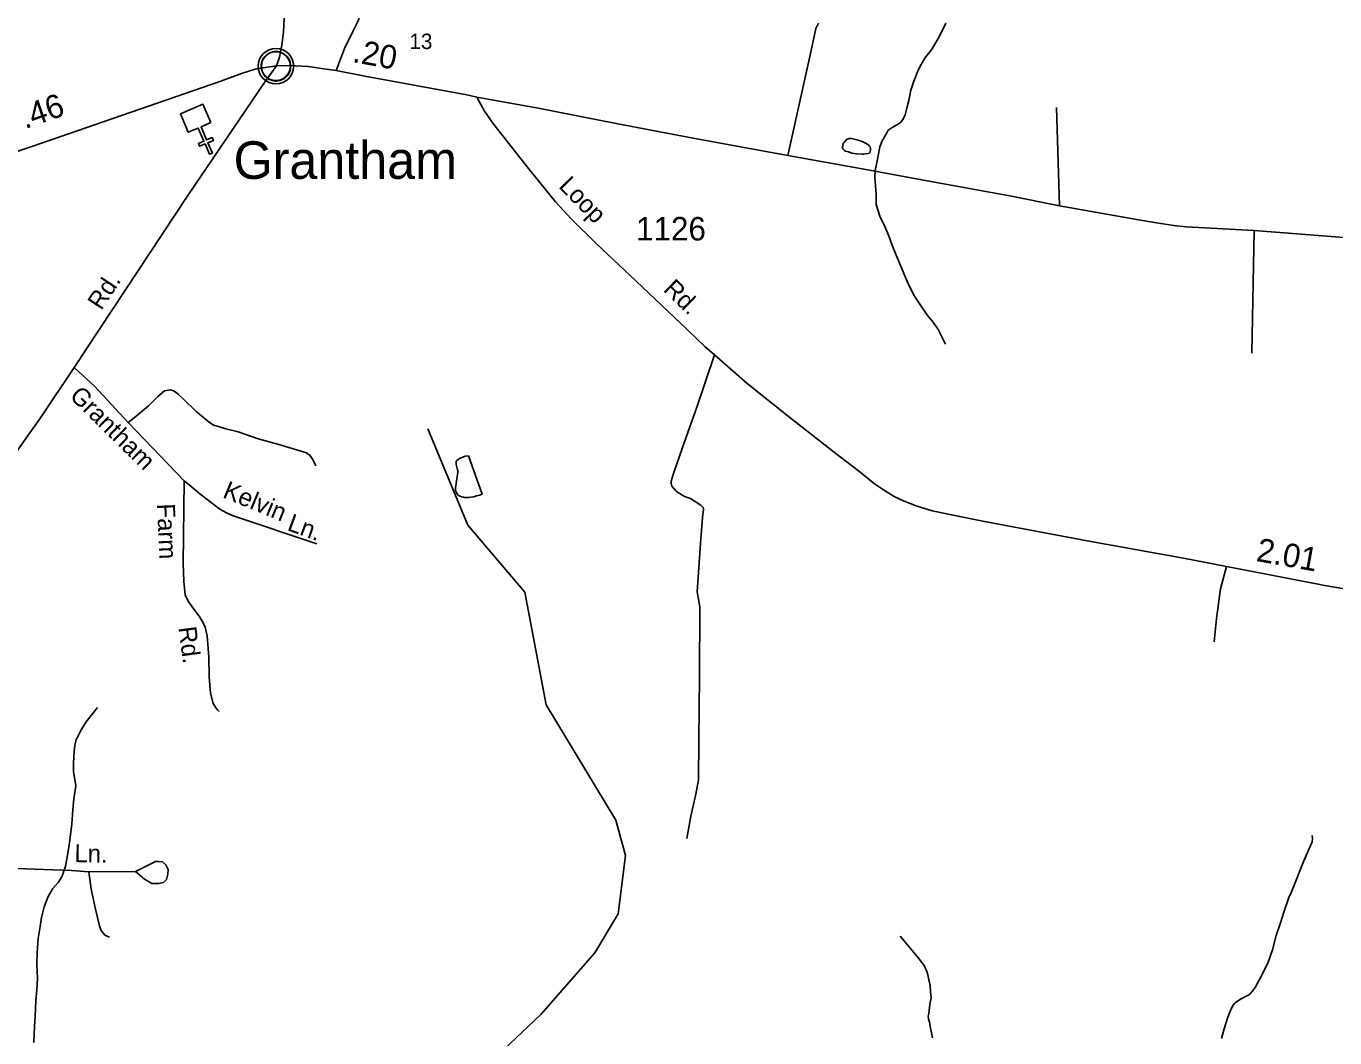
# Model space of a CAD drawing. Extents: x 2206922 to 2357709, y 510027 to 673830.
# Drawn here: x 2248244 to 2255208, y 558977 to 564362 of the extents above; entities that cross this region are included whole.
import ezdxf

# ---------------------------------------------------------------- set-up
doc = ezdxf.new("R2010")
doc.units = 0
for name, color, linetype in [('Exist Civil Demographics Community CELL', 7, 'Continuous'), ('Exist Civil Demographics Community Label', 7, 'Continuous'), ('Exist Cultural Church CELL', 7, 'Continuous'), ('Exist Hydrographic Misc Water Feature', 7, 'Continuous'), ('Exist Road Non-System Type 51', 7, 'Continuous'), ('Exist Road Non-System Type 51 Label', 7, 'Continuous'), ('Exist Road Primary US Attributed', 7, 'Continuous'), ('Exist Road Primary US Label', 7, 'Continuous'), ('Exist Road Primary US Mileage Hundredths English Label', 7, 'Continuous'), ('Exist Road Secondary Mileage Hundredths English Label', 7, 'Continuous'), ('Exist Road Secondary Type 51 Attributed', 7, 'Continuous'), ('Exist Road Secondary Type 51 Label', 7, 'Continuous'), ('Exist Road Secondary Type 51 Number Label', 7, 'Continuous')]:
    doc.layers.add(name, color=color, linetype=linetype)

msp = doc.modelspace()

# ---------------------------------------------------------------- linework, layer by layer
at = {"layer": 'Exist Civil Demographics Community CELL'}
msp.add_lwpolyline([(2249495.4, 564161.4), (2249496.4, 564167), (2249498.2, 564173.6), (2249501.1, 564180.8), (2249504, 564186.5), (2249507.4, 564192.3), (2249511.1, 564197.4), (2249515.1, 564201.8), (2249519.7, 564206.4), (2249525.2, 564211), (2249530.7, 564214.6), (2249535.5, 564217.5), (2249540.6, 564219.9), (2249546, 564222.2), (2249551.7, 564224), (2249556, 564225.2), (2249560.9, 564225.9), (2249565, 564226.7), (2249571.4, 564226.9), (2249575.8, 564226.8), (2249581.4, 564226.6), (2249586.4, 564225.8), (2249591.3, 564224.8), (2249596.3, 564223.4), (2249601.4, 564221.5), (2249608.1, 564218.6), (2249614.3, 564215.1), (2249619.4, 564211.5), (2249624.6, 564207.5), (2249627.9, 564204.4), (2249632, 564200), (2249635.9, 564195.3), (2249638.9, 564190.7), (2249642.1, 564185.7), (2249644.5, 564180.5), (2249646.6, 564175.5), (2249648.1, 564170.5), (2249649.4, 564165.9), (2249650.5, 564159.9), (2249651.1, 564155.2), (2249651.4, 564149.2), (2249651.2, 564143.4), (2249650.6, 564137.7), (2249649.7, 564132.2), (2249648.1, 564126.1), (2249646.2, 564120.2), (2249643.9, 564115.2), (2249640.7, 564109.2), (2249637.4, 564103.8), (2249634, 564099.1), (2249629.8, 564094.4), (2249624.5, 564089.4), (2249619.5, 564085.3), (2249614.5, 564081.9), (2249610.1, 564079.4), (2249603.3, 564076.1), (2249596.2, 564073.4), (2249590.2, 564071.9), (2249583.6, 564070.6), (2249579.2, 564070.2), (2249574.7, 564069.9), (2249569.1, 564069.9), (2249564.8, 564070.3), (2249559.2, 564071.1), (2249553.3, 564072.4), (2249548.7, 564073.7), (2249543.5, 564075.5), (2249538.9, 564077.5), (2249535, 564079.8), (2249528.2, 564083.8), (2249522.6, 564088.1), (2249517.7, 564092.6), (2249513.2, 564097.5), (2249510.1, 564101.4), (2249507.1, 564105.6), (2249503, 564112.7), (2249501.3, 564116.2), (2249499.6, 564120.3), (2249497, 564128.5), (2249495.4, 564135.5), (2249494.8, 564140.7), (2249494.4, 564147), (2249494.4, 564151.7), (2249494.9, 564158.1)], close=True, dxfattribs=at)
for centre, radius in [((2249573, 564149), 94.3), ((2249572.8, 564149.3), 76.7)]:
    msp.add_circle(centre, radius, dxfattribs=at)
at = {"layer": 'Exist Cultural Church CELL'}
msp.add_lwpolyline([(2249226.3, 563848.6), (2249174.1, 563826), (2249204.2, 563756.1), (2249233.6, 563768.7), (2249239.9, 563754.1), (2249210.5, 563741.4), (2249234.4, 563686.2), (2249219.6, 563679.8), (2249195.8, 563735), (2249166.4, 563722.4), (2249160.1, 563737), (2249189.5, 563749.7), (2249159.4, 563819.6), (2249106.4, 563796.9), (2249064.2, 563894.7), (2249184.2, 563946.4)], close=True, dxfattribs=at)
at = {"layer": 'Exist Hydrographic Misc Water Feature'}
for points in [[(2253136.7, 562669.2), (2253096.1, 562747.1), (2253069.4, 562786.8), (2253040.9, 562822.3), (2252998.7, 562882.2), (2252966.7, 562929.6), (2252931.6, 563003.4), (2252911.3, 563055.1), (2252882.8, 563121.1), (2252858.2, 563182.8), (2252832.2, 563250.4), (2252813.5, 563296.2), (2252787.1, 563350), (2252766.8, 563411.9), (2252766.4, 563468), (2252759.4, 563555.8), (2252761.4, 563593.6), (2252769.2, 563627.7), (2252782, 563691.9), (2252785.8, 563719.7), (2252799.6, 563752.1), (2252821.7, 563790.1), (2252831.6, 563808.1), (2252851.3, 563822.5), (2252880.8, 563838.8), (2252897, 563848.9), (2252910.5, 563866.7), (2252921, 563890.7), (2252930, 563925), (2252940, 563966.9), (2252945.6, 563993.2), (2252951.5, 564021.1), (2252967.1, 564069.1), (2252986.6, 564119.2), (2253000.5, 564149.6), (2253026.2, 564191.5), (2253065.7, 564242), (2253105.1, 564312.3), (2253138.5, 564378.6)], [(2252623.7, 563764.4), (2252635.5, 563764.6), (2252649.9, 563760.9), (2252671.8, 563755.1), (2252692.1, 563747.2), (2252710, 563739.2), (2252726.2, 563729.5), (2252729.7, 563725.3), (2252734.2, 563719.3), (2252736.2, 563713.3), (2252736.2, 563707.7), (2252736.4, 563701.6), (2252734.2, 563695.5), (2252734.4, 563691.4), (2252730.3, 563685.5), (2252722.3, 563683.4), (2252710.4, 563683.2), (2252700.3, 563681.1), (2252692.1, 563681.1), (2252664.5, 563682.8), (2252638.2, 563686.7), (2252620.6, 563692.7), (2252604.2, 563696.4), (2252598.4, 563700.5), (2252594.1, 563704.4), (2252590, 563708.2), (2252588, 563714.2), (2252590, 563726.5), (2252592.1, 563738.4), (2252596.2, 563742.2), (2252599.9, 563746.5), (2252604.2, 563752.4), (2252607.9, 563756.3), (2252612, 563760.5), (2252617.7, 563762.5), (2252623.7, 563764.4)], [(2250677.5, 556575.6), (2250643.5, 556760), (2250532.5, 556981.9), (2250530.5, 557283.7), (2250634.4, 557750.6), (2250640.4, 558058.8), (2250496.4, 558432.3), (2250544.4, 558624.9), (2250618.4, 558757.8), (2250982.4, 559101.4), (2251270.5, 559430.1), (2251394.4, 559637.5), (2251433.5, 559948.3), (2251381.4, 560136.3), (2251010.5, 560750.5), (2250897.5, 561349.8), (2250594.5, 561706.8), (2250381.4, 562219.4)], [(2250624.6, 561857.4), (2250610.7, 561855), (2250598.4, 561852.8), (2250586.5, 561853), (2250576.2, 561852.9), (2250570.7, 561855), (2250562.5, 561856.6), (2250552.4, 561860.5), (2250544.6, 561864.5), (2250536, 561874.3), (2250532.1, 561884.3), (2250528, 561890.5), (2250528, 561902.3), (2250530.1, 561914.6), (2250533.8, 561940.4), (2250541.3, 561988.3), (2250541.1, 561994.4), (2250539.1, 562000.4), (2250532.7, 562028.5), (2250531.1, 562038.1), (2250531.1, 562046.2), (2250535.2, 562050.5), (2250542.6, 562056.3), (2250550.4, 562060.3), (2250558.8, 562064.4), (2250566.6, 562068.4), (2250580.5, 562072.8), (2250596.7, 562074.9), (2250670.3, 561871.6), (2250656.2, 561865.6), (2250640.6, 561861.4), (2250624.6, 561857.4)], [(2248624.1, 560735.6), (2248563.4, 560658.8), (2248549.5, 560637), (2248535.9, 560616.7), (2248519.9, 560584.7), (2248509.9, 560562.7), (2248502.3, 560534.6), (2248496.8, 560480.7), (2248495.1, 560430.7), (2248495.5, 560394.5), (2248508.1, 560318.8), (2248496.8, 560248.7), (2248491.2, 560190.8), (2248487.5, 560116.7), (2248476.7, 560028.7), (2248465, 559958.7), (2248453.3, 559890.4), (2248436.1, 559838.2), (2248414.1, 559804.2), (2248386.3, 559771.9), (2248361, 559729.9), (2248339.7, 559675.5), (2248325.8, 559617.6), (2248318.2, 559569.7), (2248306.7, 559505.3), (2248301.6, 559433.5), (2248299.9, 559365.6), (2248304.4, 559295.6), (2248300.9, 559233.7), (2248295.6, 559173.6), (2248292.1, 559091.4), (2248288.6, 559037.6), (2248285, 558951.8)], [(2255086.5, 560054.4), (2255089.2, 560038.7), (2255086.9, 560020.7), (2255042.2, 559920), (2254977, 559753.8), (2254963.5, 559723.9), (2254938.3, 559651.4), (2254918.6, 559589.5), (2254895.4, 559521.2), (2254875.9, 559445.1), (2254852.6, 559380.9), (2254819.1, 559310.5), (2254783.5, 559244.5), (2254773.8, 559230.5), (2254757.6, 559212.3), (2254746.1, 559204.3), (2254706.2, 559184), (2254678.1, 559163.5), (2254666.4, 559151.5), (2254656.7, 559131.5), (2254638.7, 559087.5), (2254619.4, 559025.1), (2254604, 558973.1)], [(2252894.3, 559518.8), (2252922.2, 559485), (2252948.9, 559453.4), (2252993, 559401.7), (2253009.4, 559377.8), (2253021.7, 559362.1), (2253027.8, 559350.2), (2253035.6, 559336.1), (2253041.8, 559312.1), (2253046.5, 559286.2), (2253054.7, 559256.2), (2253056.5, 559222.2), (2253059, 559190.6), (2253053.2, 559156.2), (2253051.2, 559138.3), (2253047.5, 559106.4), (2253043.8, 559092.3), (2253045.9, 559078.2), (2253050.2, 559060.6), (2253056.1, 559030.5), (2253066.8, 558976.6)]]:
    msp.add_lwpolyline(points, dxfattribs=at)
at = {"layer": 'Exist Road Non-System Type 51'}
for p, q in [((2253741.8, 563406.5), (2253726.4, 563929.3)), ((2254766.4, 562621.2), (2254778.6, 563273.5)), ((2249084.4, 561942.2), (2248786, 562252.7)), ((2248825.9, 559863.2), (2248576.6, 559861.2))]:
    msp.add_line(p, q, dxfattribs=at)
for points in [[(2249892.5, 564126), (2249937.6, 564242.2), (2249984.7, 564336.6), (2250004.4, 564378.8), (2250014.4, 564398.8), (2250012, 564430.8), (2250005.4, 564498.8), (2250009, 564568.7), (2250014.4, 564638.7), (2250018, 564686.6), (2250019.9, 564700.6), (2250033.5, 564740.7), (2250082.9, 564819.1)], [(2252297.3, 563672.7), (2252363.7, 563977.6), (2252416.8, 564216.3), (2252445.7, 564350.1), (2252459.4, 564377.5)], [(2251760.3, 560039.2), (2251780, 560157.8), (2251807.4, 560274.9), (2251821.1, 560350.9), (2251822.6, 560562.3), (2251827.2, 560898.3), (2251828.7, 561270.9), (2251815, 561351.5), (2251831.7, 561608.4), (2251842.4, 561746.8), (2251848.2, 561791.1), (2251846.1, 561800.6), (2251834.8, 561812.2), (2251778.5, 561847.2), (2251746.6, 561859.3), (2251728.5, 561869.2), (2251707.5, 561884.3), (2251703.1, 561887.7), (2251679.7, 561914.1), (2251675.7, 561927.8), (2251675.2, 561939.9), (2251687.3, 561976.4), (2251736, 562119.4), (2251813.5, 562333.8), (2251906.2, 562612.1)], [(2248786, 562252.7), (2248607.3, 562446.2), (2248498.4, 562545.1)], [(2249785, 562021.4), (2249768.4, 562054.7), (2249761, 562067.6), (2249753.6, 562078.7), (2249742.5, 562086.1), (2249735.1, 562091.6), (2249694.4, 562102.7), (2249589.1, 562136), (2249478.2, 562165.6), (2249371, 562202.6), (2249306.3, 562219.2), (2249267.5, 562230.3), (2249239.8, 562237.7), (2249210.2, 562259.9), (2249147.4, 562313.5), (2249079, 562378.3), (2249054.5, 562400.8), (2249042.2, 562411.4), (2249027.2, 562420.3), (2249011.1, 562425.9), (2248979.9, 562421.4), (2248943.8, 562391.4), (2248894.2, 562341.3), (2248818.4, 562276.6), (2248786, 562252.7)], [(2249084.4, 561942.2), (2249079.6, 561504), (2249082, 561405.7), (2249090.3, 561335.8), (2249098.6, 561315.6), (2249111.6, 561293.1), (2249119.9, 561281.3), (2249135.3, 561258.8), (2249163.7, 561220.9), (2249185, 561186.5), (2249196.8, 561162.9), (2249207.5, 561117.8), (2249215.8, 561003), (2249218.1, 560898.7), (2249225.2, 560812.3), (2249239.5, 560756.6), (2249254.8, 560731.7), (2249261.9, 560723.4), (2249270.2, 560714)], [(2249791.1, 561605.8), (2249344.8, 561755.1), (2249309.3, 561771.6), (2249275, 561791.8), (2249227.6, 561826.1), (2249167.2, 561873.5), (2249122.3, 561911.4), (2249084.4, 561942.2)], [(2254565.8, 561085.3), (2254578, 561208.5), (2254599.2, 561366.7), (2254631.2, 561485.3)], [(2248576.6, 559861.2), (2248485.4, 559868.3), (2247846.2, 559890.8), (2247384.5, 559906.2), (2247223.5, 559907.4), (2247164.3, 559914.5), (2247109.9, 559922.8), (2247076.1, 559937)], [(2248825.9, 559863.2), (2248931.3, 559916.1), (2248949.3, 559916.3), (2248969.3, 559914.5), (2248987.5, 559898.5), (2248999.6, 559872.7), (2248997.9, 559848.7), (2248990.2, 559820.7), (2248974.2, 559804.4), (2248948.3, 559798.4), (2248912.3, 559798.1), (2248874.2, 559821.6), (2248825.9, 559863.2)], [(2248576.6, 559861.2), (2248589.6, 559769.4), (2248612.1, 559662.8), (2248633.4, 559574), (2248642.8, 559548.5), (2248663, 559524.2), (2248686.6, 559513.6)]]:
    msp.add_lwpolyline(points, dxfattribs=at)
at = {"layer": 'Exist Road Primary US Attributed'}
for points in [[(2247268.5, 563382.4), (2248278.6, 563722.9), (2249084, 564001.3), (2249279.3, 564069), (2249388.9, 564109.7), (2249462.8, 564132.4), (2249504.7, 564140.8), (2249576.5, 564151.3)], [(2249576.5, 564151.3), (2249642.5, 564151.8), (2249744.6, 564146.7), (2249828.5, 564135.4), (2249892.5, 564126), (2250046.8, 564095.2), (2250589.3, 563995.7), (2250642, 563984.6)], [(2250642, 563984.6), (2250959.8, 563926.6), (2251383.8, 563844.3), (2251792.7, 563765.1), (2252297.3, 563672.7), (2252692, 563603.4), (2253077.8, 563530.8), (2253486.3, 563457.5), (2253741.8, 563406.5), (2254163.1, 563331.3), (2254258.8, 563314.6), (2254351.5, 563300.9), (2254416.9, 563293.3), (2254778.6, 563273.5), (2255279.3, 563236.1), (2256037.4, 563182.4), (2256635.4, 563141.3), (2256953.4, 563126), (2257076.5, 563118.4), (2257768, 563063.7), (2257898.7, 563045.4), (2258552.2, 562960.3), (2259081.1, 562884.2)]]:
    msp.add_lwpolyline(points, dxfattribs=at)
at = {"layer": 'Exist Road Secondary Type 51 Attributed'}
for points in [[(2249576.5, 564151.3), (2249592, 564197.4), (2249604.6, 564260.6), (2249613.6, 564332.3), (2249616.1, 564400.1), (2249600.8, 564769.8), (2249586.7, 565008.4), (2249562.4, 565412.7), (2249558, 565680.4), (2249561.2, 565780.4), (2249568.4, 565870.4), (2249596.8, 566068.5), (2249648.3, 566376.8), (2249736.1, 566895.3), (2249782.4, 567233.9), (2249790.1, 567292.7)], [(2246051.8, 556756.8), (2246064.4, 556788.3), (2246513.3, 558143.2), (2246748.8, 558892.9), (2247076.1, 559937), (2247140.7, 560160.3), (2247185.6, 560316.6), (2247227.1, 560441.5), (2247291, 560613.3), (2247372.7, 560802.8), (2247415.3, 560907), (2247502.9, 561056.3), (2247655.8, 561326), (2247768, 561513.4), (2247919.6, 561731.4), (2248045.4, 561908), (2248159.9, 562052.3), (2248319.7, 562278), (2248498.4, 562545.1), (2249103.3, 563461.2), (2249516.4, 564068.2), (2249576.5, 564151.3)], [(2250642, 563984.6), (2250663.7, 563944.4), (2250683.5, 563909.2), (2250731.9, 563838.8), (2250923.2, 563595.7), (2251060.6, 563427.4), (2251144.1, 563337.2), (2251278.3, 563203), (2251488.2, 563006.1), (2251624.5, 562876.3), (2251763.1, 562746.5), (2251854.5, 562656.7), (2251906.2, 562612.1), (2252081, 562460), (2252316.5, 562271.4), (2252552.1, 562087.4), (2252672.2, 561994.7), (2252758.8, 561926.3), (2252812, 561891.3), (2252862.1, 561859.3), (2252916.8, 561833.5), (2252979.2, 561809.2), (2253064.3, 561781.8), (2253176.7, 561759), (2253343.9, 561725.5), (2253909.3, 561619.1), (2254401.7, 561529.7), (2254631.2, 561485.3), (2255118.5, 561391.7), (2255144.2, 561387.1)], [(2255144.2, 561387.1), (2255300.6, 561359.2)]]:
    msp.add_lwpolyline(points, dxfattribs=at)

# ---------------------------------------------------------------- texts
at = {"layer": 'Exist Civil Demographics Community Label'}
msp.add_text('Grantham', height=200, dxfattribs=at).set_placement((2249347.4, 563549))
at = {"layer": 'Exist Road Non-System Type 51 Label'}
for s, rotation, p in [('Grantham', 315.47178, (2248470, 562387.9)), ('Kelvin', 337.59771, (2249284.4, 561855.8)), ('Farm', 272.36703, (2248940, 561819.4)), ('Ln.', 339.88993, (2249628, 561680.8)), ('Rd.', 277.57749, (2249053.7, 561161.1)), ('Ln.', 358.96066, (2248500.1, 559912.8))]:
    msp.add_text(s, height=95, rotation=rotation, dxfattribs=at).set_placement(p)
at = {"layer": 'Exist Road Primary US Label'}
msp.add_text('13', height=82.02, dxfattribs=at).set_placement((2250283.5, 564240.1))
at = {"layer": 'Exist Road Primary US Mileage Hundredths English Label'}
for s, rotation, p in [('.20', 349.60709, (2249975.6, 564171.8)), ('.46', 19.06849, (2248237.5, 563813.9))]:
    msp.add_text(s, height=125, rotation=rotation, dxfattribs=at).set_placement(p)
at = {"layer": 'Exist Road Secondary Mileage Hundredths English Label'}
msp.add_text('2.01', height=125, rotation=349.88076, dxfattribs=at).set_placement((2254784.7, 561516))
at = {"layer": 'Exist Road Secondary Type 51 Label'}
for s, rotation, p in [('Loop', 314.45745, (2251073, 563506.4)), ('Rd.', 56.61916, (2248643.2, 562844.9)), ('Rd.', 315.9627, (2251630.1, 562956))]:
    msp.add_text(s, height=95, rotation=rotation, dxfattribs=at).set_placement(p)
at = {"layer": 'Exist Road Secondary Type 51 Number Label'}
msp.add_text('1126', height=125, dxfattribs=at).set_placement((2251489.1, 563221.2))

doc.saveas('drawing.dxf')
